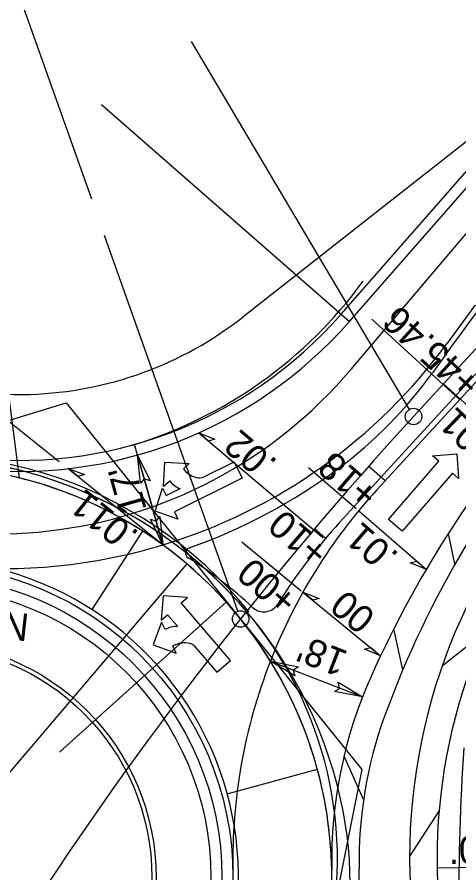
# Model space of a CAD drawing. Extents: x 1761082 to 1764358, y 421907 to 425434.
# Drawn here: x 1762724.8 to 1762805.2, y 423617.8 to 423773.7 of the extents above; entities that cross this region are included whole.
import ezdxf

# ---------------------------------------------------------------- set-up
doc = ezdxf.new("R2010")
doc.units = 0
for name, color, linetype in [('MARK HOOKS CENTER STRAIGHT LEFT TURN ARROW CELL', 7, 'Continuous'), ('MARK LEFT TURN ARROW CELL', 7, 'Continuous'), ('MARK STRAIGHT RIGHT ARROW CELL', 7, 'Continuous'), ('MARK UTURN ARROW CELL', 7, 'Continuous'), ('Prop Mkg 3ft Min Skp 3ft Wide White', 7, 'Continuous'), ('Prop Mkg 3ft Min Skp 9ft White', 7, 'Continuous'), ('Prop Mkg 3ft Min Skp 9ft Wide White', 7, 'Continuous'), ('Prop Mkg Min Skp 6ft Yellow', 7, 'Continuous'), ('Prop Mkg Skp Wht', 7, 'Continuous'), ('Prop Mkg Solid White Diagonals', 7, 'Continuous'), ('Prop Mkg Solid White Edge Line', 7, 'Continuous'), ('Prop Mkg Solid White Gore Line', 7, 'Continuous'), ('Prop Mkg Solid White Lane Line', 7, 'Continuous'), ('Prop Mkg Solid White Multiple Diagonals V8i', 7, 'Continuous'), ('Prop Mkg Solid White Wide Lane Line', 7, 'Continuous'), ('Prop Mkg Solid Yel Skip LT', 7, 'Continuous'), ('Prop Mkg Solid Yel Skip RT', 7, 'Continuous'), ('Prop Mkg Solid Yellow Diagonals', 7, 'Continuous'), ('Prop Mkg Solid Yellow Edge Line', 7, 'Continuous'), ('Prop Mkg Solid Yellow Lane Line', 7, 'Continuous'), ('Prop Mkr Yel 80ft Spc', 7, 'Continuous'), ('Scratch_Level_0', 7, 'Continuous'), ('Scratch_Level_1', 7, 'Continuous'), ('Scratch_Level_5', 7, 'Continuous')]:
    doc.layers.add(name, color=color, linetype=linetype)

msp = doc.modelspace()

# ---------------------------------------------------------------- linework, layer by layer
at = {"layer": 'MARK HOOKS CENTER STRAIGHT LEFT TURN ARROW CELL'}
for p, q in [((1762772.35, 423672.59), (1762768.49, 423675.76)), ((1762762.81, 423667.14), (1762759.1, 423663.8))]:
    msp.add_line(p, q, dxfattribs=at)
at = {"layer": 'MARK LEFT TURN ARROW CELL'}
msp.add_line((1762783.77, 423719.57), (1762897.35, 423849.4), dxfattribs=at)
msp.add_arc((1762725.06, 423770.93), 78, 262.5595, 318.8196, dxfattribs=at)
at = {"layer": 'MARK STRAIGHT RIGHT ARROW CELL'}
msp.add_line((1762908.06, 423822.3), (1762796.93, 423700.93), dxfattribs=at)
msp.add_arc((1763313.22, 423228.23), 700, 137.52342, 147.0162, dxfattribs=at)
at = {"layer": 'MARK UTURN ARROW CELL'}
for points in [[(1762738.34, 423740.53), (1762722.42, 423785.44)], [(1762796.17, 423702.22), (1762756.52, 423769.2)], [(1762764.95, 423665.47), (1762740.69, 423733.89)]]:
    msp.add_lwpolyline(points, dxfattribs=at)
for centre in [(1762796.93, 423700.93), (1762765.45, 423664.05)]:
    msp.add_circle(centre, 1.5, dxfattribs=at)
at = {"layer": 'Prop Mkg 3ft Min Skp 3ft Wide White'}
msp.add_line((1762796.93, 423700.93), (1762908.06, 423822.3), dxfattribs=at)
for centre, radius, start, end in [((1763313.22, 423228.23), 700, 137.52342, 147.0162), ((1762707.06, 423616.97), 75, 38.8816, 106.8512), ((1762707.06, 423616.97), 75, 348.6079, 38.8816)]:
    msp.add_arc(centre, radius, start, end, dxfattribs=at)
at = {"layer": 'Prop Mkg 3ft Min Skp 9ft White'}
msp.add_circle((1762707.06, 423616.97), 55, dxfattribs=at)
at = {"layer": 'Prop Mkg 3ft Min Skp 9ft Wide White'}
msp.add_line((1762821.72, 423762.95), (1762765.85, 423719.03), dxfattribs=at)
for centre, radius, start, end in [((1762725.5, 423780.94), 76, 233.4908, 271.2744), ((1762725.06, 423770.93), 66, 271.8465, 308.1656)]:
    msp.add_arc(centre, radius, start, end, dxfattribs=at)
at = {"layer": 'Prop Mkg Skp Wht'}
msp.add_line((1762785.28, 423718.25), (1762898.9, 423848.13), dxfattribs=at)
msp.add_arc((1762725.06, 423770.93), 80, 263.3316, 318.8196, dxfattribs=at)
at = {"layer": 'Prop Mkg Solid White Diagonals'}
msp.add_line((1762783.48, 423681.64), (1763081.76, 424007.42), dxfattribs=at)
for radius in [53, 43]:
    msp.add_circle((1762707.06, 423616.97), radius, dxfattribs=at)
for centre, radius, start, end in [((1763611.44, 423125.64), 999, 138.81963, 144.27858), ((1762735.44, 423755.61), 80, 306.7639, 324.2786), ((1762960.85, 423584.88), 180, 138.0009, 160.0358), ((1762722.27, 423773.24), 102, 289.3687, 306.7639), ((1762902.22, 423620.56), 106, 137.2008, 182.9577), ((1762857.24, 423614.11), 100, 137.5234, 148.218), ((1762756.43, 423676.06), 1, 173.8725, 237.6587), ((1762756.43, 423676.06), 1, 109.3687, 173.8725), ((1762713.1, 423607.63), 80, 47.0247, 57.6587), ((1762769.68, 423668.36), 3, 227.0247, 328.218), ((1762864.03, 423620.05), 77, 160.0358, 181.1223), ((1762707.06, 423616.97), 80, 359.4391, 1.1238)]:
    msp.add_arc(centre, radius, start, end, dxfattribs=at)
at = {"layer": 'Prop Mkg Solid White Edge Line'}
for p, q in [((1762740.12, 423757.76), (1762785.28, 423718.25)), ((1762751.3, 423677.54), (1762746.16, 423695.83))]:
    msp.add_line(p, q, dxfattribs=at)
for centre, radius, start, end in [((1762722.27, 423773.24), 81, 286.8732, 323.9337), ((1762707.06, 423616.97), 77, 38.8816, 106.8512), ((1762707.06, 423616.97), 75, 38.8816, 106.8512), ((1762707.06, 423616.97), 75, 348.6079, 38.8816)]:
    msp.add_arc(centre, radius, start, end, dxfattribs=at)
at = {"layer": 'Prop Mkg Solid White Gore Line'}
for radius in [43, 42.25]:
    msp.add_circle((1762707.06, 423616.97), radius, dxfattribs=at)
at = {"layer": 'Prop Mkg Solid White Lane Line'}
msp.add_line((1762783.48, 423681.64), (1763081.76, 424007.42), dxfattribs=at)
for centre, radius, start, end in [((1763611.44, 423125.64), 999, 138.81963, 144.27858), ((1762735.44, 423755.61), 80, 306.7639, 324.2786), ((1762960.85, 423584.88), 180, 138.0009, 160.0358), ((1762722.27, 423773.24), 102, 289.3687, 306.7639), ((1762902.22, 423620.56), 106, 137.2008, 182.9577), ((1762857.24, 423614.11), 100, 137.5234, 148.218), ((1762756.43, 423676.06), 1, 109.3687, 237.6587), ((1762713.1, 423607.63), 80, 47.0247, 57.6587), ((1762769.68, 423668.36), 3, 227.0247, 328.218), ((1762864.03, 423620.05), 77, 160.0358, 181.1223), ((1762707.06, 423616.97), 80, 359.4391, 1.1238)]:
    msp.add_arc(centre, radius, start, end, dxfattribs=at)
at = {"layer": 'Prop Mkg Solid White Multiple Diagonals V8i'}
for p, q in [((1762828.21, 423683.26), (1762802.4, 423706.9)), ((1762474.81, 423624.99), (1762733.71, 423703.41)), ((1762733.71, 423703.41), (1762787.54, 423636.66)), ((1762791.77, 423689.2), (1762788.77, 423691.85)), ((1762738.43, 423665.76), (1762747.62, 423680.06)), ((1762732.45, 423639.81), (1762762.81, 423667.14)), ((1762763.02, 423632.23), (1762779.43, 423636.7)), ((1762787.54, 423636.66), (1762780.59, 423602.16))]:
    msp.add_line(p, q, dxfattribs=at)
for radius in [57, 53]:
    msp.add_circle((1762707.06, 423616.97), radius, dxfattribs=at)
for centre, radius, start, end in [((1762722.27, 423773.24), 100, 264.4409, 286.8732), ((1762707.06, 423616.97), 58, 332.6013, 110.42), ((1762864.03, 423620.05), 100, 158.6908, 181.123), ((1762707.06, 423616.97), 75, 1.123, 31.7062)]:
    msp.add_arc(centre, radius, start, end, dxfattribs=at)
at = {"layer": 'Prop Mkg Solid White Wide Lane Line'}
msp.add_line((1762755.65, 423674.11), (1762707.06, 423616.97), dxfattribs=at)
msp.add_circle((1762783.65, 423631.3), 0.0417, dxfattribs=at)
msp.add_circle((1762783.65, 423631.3), 0.0417, dxfattribs=at)
for centre, radius, start, end in [((1762705.65, 423613.56), 80, 12.8164, 194.1392), ((1762715.4, 423615.77), 70, 314.7787, 12.8164)]:
    msp.add_arc(centre, radius, start, end, dxfattribs=at)
at = {"layer": 'Prop Mkg Solid Yel Skip RT'}
for p, q in [((1762789.35, 423718.63), (1762805.32, 423704.01)), ((1762702.64, 423716.55), (1762732.44, 423692.71)), ((1762746.7, 423693.91), (1762751.3, 423677.54)), ((1762777.8, 423691.67), (1762786.49, 423684.16)), ((1762771.65, 423686.28), (1762780.41, 423678.87)), ((1762765.65, 423678.09), (1762776.5, 423669.18)), ((1762770.87, 423656.39), (1762787.64, 423649.85))]:
    msp.add_line(p, q, dxfattribs=at)
at = {"layer": 'Prop Mkg Solid Yellow Diagonals'}
for p, q in [((1762800.39, 423693.75), (1762804.8, 423694.11)), ((1762801.52, 423692.77), (1762800.39, 423693.75)), ((1762804.8, 423694.11), (1762805.15, 423689.63)), ((1762751.43, 423688.18), (1762751.68, 423692.6)), ((1762751.68, 423692.6), (1762756.11, 423692.35)), ((1762756.11, 423692.35), (1762755.03, 423691.37)), ((1762758.49, 423689.8), (1762764.27, 423692.67)), ((1762764.27, 423692.67), (1762765.74, 423689.72)), ((1762792.36, 423682.18), (1762801.52, 423692.77)), ((1762804.02, 423690.61), (1762794.86, 423680.03)), ((1762805.15, 423689.63), (1762804.02, 423690.61)), ((1762752.54, 423689.18), (1762751.43, 423688.18)), ((1762765.74, 423689.72), (1762753.39, 423683.57)), ((1762749.88, 423683.66), (1762751.25, 423687.86)), ((1762751.25, 423687.86), (1762751.91, 423686.52)), ((1762751.91, 423686.52), (1762754.47, 423687.79)), ((1762754.05, 423682.23), (1762749.88, 423683.66)), ((1762753.39, 423683.57), (1762754.05, 423682.23)), ((1762794.86, 423680.03), (1762792.36, 423682.18)), ((1762751.38, 423668.26), (1762751.01, 423663.85)), ((1762755.79, 423667.95), (1762751.38, 423668.26)), ((1762754.65, 423666.98), (1762755.79, 423667.95)), ((1762763.62, 423656.49), (1762754.65, 423666.98)), ((1762751.01, 423663.85), (1762752.14, 423664.83)), ((1762752.14, 423664.83), (1762754, 423662.66)), ((1762751.05, 423663.5), (1762749.55, 423659.32)), ((1762751.69, 423662.13), (1762751.05, 423663.5)), ((1762749.55, 423659.32), (1762753.73, 423657.83)), ((1762753.73, 423657.83), (1762753.12, 423659.15)), ((1762756.92, 423659.25), (1762761.12, 423654.34)), ((1762761.12, 423654.34), (1762763.62, 423656.49))]:
    msp.add_line(p, q, dxfattribs=at)
for centre, radius, start, end in [((1762758.52, 423694.11), 4.43, 218.1837, 249.0372), ((1762757.98, 423692.27), 2.52, 245.5471, 281.8591), ((1762756.04, 423691.92), 4.43, 218.0648, 248.9434), ((1762753.84, 423658.25), 4.43, 88.0813, 118.9599), ((1762755.26, 423655.26), 4.43, 87.9875, 118.8411), ((1762755.48, 423657.17), 2.52, 55.1656, 91.4776)]:
    msp.add_arc(centre, radius, start, end, dxfattribs=at)
at = {"layer": 'Prop Mkg Solid Yellow Edge Line'}
msp.add_arc((1762707.06, 423616.97), 75, 53.8578, 83.3316, dxfattribs=at)
at = {"layer": 'Prop Mkg Solid Yellow Lane Line'}
for points in [[(1762747.24, 423688.76), (1762746.7, 423693.91), (1762748.96, 423689.21), (1762747.91, 423689.59)], [(1762750.77, 423682.69), (1762751.3, 423677.54), (1762749.04, 423682.24), (1762750.09, 423681.85)], [(1762775.31, 423653.72), (1762770.87, 423656.39), (1762775.98, 423655.37), (1762775.04, 423654.76)], [(1762783.21, 423652.52), (1762787.64, 423649.85), (1762782.53, 423650.87), (1762783.47, 423651.48)]]:
    msp.add_lwpolyline(points, close=True, dxfattribs=at)
at = {"layer": 'Prop Mkr Yel 80ft Spc'}
msp.add_circle((1762765.14, 423667.04), 0.0417, dxfattribs=at)
msp.add_circle((1762765.14, 423667.04), 0.0417, dxfattribs=at)
for centre, radius, start, end in [((1762705.65, 423613.56), 80, 41.9526, 96.3138), ((1762713.08, 423620.24), 70, 347.6498, 41.9523)]:
    msp.add_arc(centre, radius, start, end, dxfattribs=at)
at = {"layer": 'Scratch_Level_0'}
for p, q in [((1762790.28, 423687.58), (1763082.58, 424006.83)), ((1762780.93, 423678.74), (1762778.9, 423680.45)), ((1762804.48, 423674.05), (1762803.27, 423679.63)), ((1762794.99, 423654.82), (1762793.35, 423662.28)), ((1762802.16, 423655.53), (1762809.99, 423661.73)), ((1762787.84, 423631.16), (1762784.28, 423639.1)), ((1762796.22, 423620.73), (1762801.58, 423629.07))]:
    msp.add_line(p, q, dxfattribs=at)
for centre, radius, start, end in [((1763611.44, 423125.64), 1000, 138.81963, 143.93371), ((1762722.27, 423773.24), 100, 286.8732, 323.9337), ((1762971.73, 423571.82), 200, 137.5234, 155.8731), ((1762864.03, 423620.05), 100, 137.5234, 158.6908), ((1762902.22, 423620.56), 101, 139.7301, 182.9577), ((1762707.06, 423616.97), 75, 31.7062, 53.8578), ((1762864.03, 423620.05), 82, 155.8731, 181.123), ((1762707.06, 423616.97), 75, 359.4399, 1.123)]:
    msp.add_arc(centre, radius, start, end, dxfattribs=at)
at = {"layer": 'Scratch_Level_1'}
msp.add_line((1762785.64, 423709.58), (1762903.23, 423848.39), dxfattribs=at)
msp.add_lwpolyline([(1762725.19, 423689.75), (1762700.56, 423881.1), (1762754, 423944.18)], dxfattribs=at)
for centre in [(1762785.64, 423709.58), (1762785.64, 423709.58), (1762765.14, 423667.04), (1762765.14, 423667.04)]:
    msp.add_circle(centre, 0.0417, dxfattribs=at)
for centre, radius, start, end in [((1762720.78, 423764.53), 85, 233.4908, 319.7301), ((1762705.65, 423613.56), 80, 41.9526, 194.1392), ((1762713.08, 423620.24), 70, 347.6498, 41.9523), ((1763305.11, 423609.67), 500, 176.4538, 179.9158)]:
    msp.add_arc(centre, radius, start, end, dxfattribs=at)
at = {"layer": 'Scratch_Level_5'}
for p, q in [((1762757.85, 423697.95), (1762771.65, 423686.28)), ((1762734.05, 423691.43), (1762751.38, 423677.57)), ((1762786.95, 423683.75), (1762799.27, 423673.09)), ((1762776.8, 423668.93), (1762790.93, 423657.33)), ((1762817.24, 423618.96), (1762801.24, 423618.66))]:
    msp.add_line(p, q, dxfattribs=at)
for points in [[(1762757.85, 423697.95), (1762760.78, 423696.78), (1762759.61, 423696.46)], [(1762734.05, 423691.43), (1762737.01, 423690.34), (1762735.85, 423689.99)], [(1762799.27, 423673.09), (1762796.34, 423674.3), (1762797.52, 423674.61)], [(1762776.8, 423668.93), (1762779.75, 423667.8), (1762778.58, 423667.47)], [(1762790.93, 423657.33), (1762788, 423658.53), (1762789.18, 423658.84)]]:
    msp.add_lwpolyline(points, close=True, dxfattribs=at)

# ---------------------------------------------------------------- texts
at = {"layer": 'Prop Mkg Min Skp 6ft Yellow'}
for s, rotation, p in [('.01', 136.2121, (1762811.35, 423696.45)), ('.02', 139.5739, (1762772.37, 423692.78)), ('.011', 141.1461, (1762747.18, 423679.74)), ('.01', 139.1213, (1762794.47, 423675.85)), ('00', 140.3924, (1762790.29, 423664.88)), ('.03', 1.0776, (1762803.37, 423619.41))]:
    msp.add_text(s, height=5, rotation=rotation, dxfattribs=at).set_placement(p)
at = {"layer": 'Prop Mkg Solid Yel Skip LT'}
for s, rotation, p in [("17'", 105.692, (1762748.4, 423684.01)), ('APRON', 353.674, (1762702.94, 423662.59)), ("18'", 158.6908, (1762785.25, 423658.05))]:
    msp.add_text(s, height=5, rotation=rotation, dxfattribs=at).set_placement(p)
at = {"layer": 'Prop Mkg Solid Yel Skip RT'}
for s, rotation, p in [('+45.46', 137.5234, (1762809.49, 423707.49)), ('+18', 139.1213, (1762790.95, 423687.45)), ('+10', 139.1213, (1762781.9, 423676.84)), ('+00', 139.1213, (1762776.24, 423668.08))]:
    msp.add_text(s, height=5, rotation=rotation, dxfattribs=at).set_placement(p)

doc.saveas('drawing.dxf')
